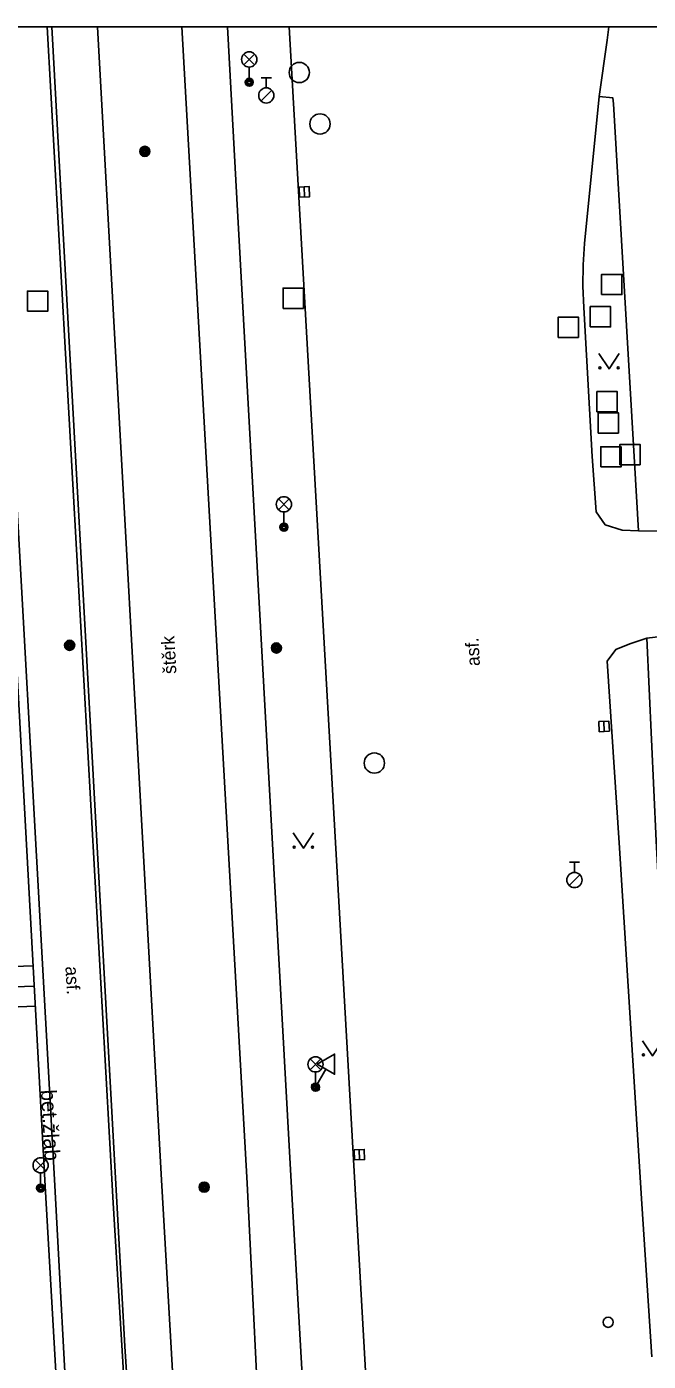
# Model space of a CAD drawing. Extents: x -599951 to -598963, y -1164095 to -1162939.
# Drawn here: x -599258.6 to -599227.9, y -1163005.2 to -1162939.4 of the extents above; entities that cross this region are included whole.
import ezdxf

# ---------------------------------------------------------------- set-up
doc = ezdxf.new("R2010")
doc.units = 0
for name, color, linetype in [('Level 10', 7, 'Continuous'), ('Level 11', 7, 'Continuous'), ('Level 13', 7, 'Continuous'), ('Level 15', 7, 'Continuous'), ('Level 25', 7, 'Continuous'), ('Level 26', 7, 'Continuous'), ('Level 27', 7, 'Continuous'), ('Level 28', 7, 'Continuous'), ('Level 33', 7, 'Continuous'), ('Level 34', 7, 'Continuous'), ('Level 36', 7, 'Continuous'), ('Level 40', 7, 'Continuous'), ('Level 42', 7, 'Continuous'), ('Level 9', 7, 'Continuous'), ('Vrstva 53', 7, 'Continuous')]:
    doc.layers.add(name, color=color, linetype=linetype)

msp = doc.modelspace()

# ---------------------------------------------------------------- linework, layer by layer
at = {"layer": 'Level 10'}
for points in [[(-599235.1, -1163108.54), (-599236.69, -1163094.1), (-599238.6, -1163065.25), (-599241.55, -1163010.92), (-599245.616, -1162939.4)], [(-599229.84, -1162939.4), (-599229.92, -1162940.07), (-599230.32, -1162942.84)], [(-599231.04, -1162950.09), (-599230.32, -1162942.84)], [(-599231.08, -1162953.26), (-599231.12, -1162952.2), (-599231.11, -1162951.15), (-599231.04, -1162950.09)], [(-599231.08, -1162953.26), (-599230.66, -1162960.61)], [(-599230.02, -1162963.97), (-599230.47, -1162963.34), (-599230.66, -1162960.61)], [(-599230.02, -1162963.97), (-599229.19, -1162964.24)], [(-599225.5, -1162964.29), (-599228.38, -1162964.28), (-599229.19, -1162964.24)], [(-599227.97, -1162969.57), (-599228.8, -1162969.84)], [(-599225.23, -1162969.24), (-599227.97, -1162969.57)], [(-599228.8, -1162969.84), (-599229.5, -1162970.13), (-599229.92, -1162970.71)], [(-599229.92, -1162970.71), (-599229.34, -1162979.66), (-599228.21, -1162997.48)], [(-599227.72, -1163005.03), (-599228.21, -1162997.48)]]:
    msp.add_lwpolyline(points, dxfattribs=at)
at = {"layer": 'Level 11'}
msp.add_line((-599257.324, -1162939.4), (-599256.84, -1162948.1), dxfattribs=at)
for points in [[(-599245.53, -1162996.1), (-599248.19, -1162947.88), (-599248.656, -1162939.4)], [(-599230.32, -1162942.84), (-599229.64, -1162942.91), (-599229.62, -1162943.2), (-599228.57, -1162960.89)], [(-599256.88, -1163010.08), (-599257.66, -1162996.31), (-599260.31, -1162948.14)], [(-599256.88, -1163010.08), (-599256.44, -1163010.06), (-599257.19, -1162996.28), (-599259.89, -1162948.12)], [(-599256.84, -1162948.1), (-599253.71, -1163004.52)], [(-599228.38, -1162964.28), (-599228.57, -1162960.89)], [(-599227.97, -1162969.57), (-599227.51, -1162979.56), (-599226.57, -1162997.39)], [(-599237.83, -1163111.49), (-599238.1, -1163108.93), (-599239.62, -1163094.44), (-599241.44, -1163069.14), (-599241.62, -1163064.75), (-599244.67, -1163011.13), (-599245.53, -1162996.1)], [(-599246.78, -1163110.11), (-599248.77, -1163090.46), (-599253.16, -1163012.98), (-599253.71, -1163004.52)]]:
    msp.add_lwpolyline(points, dxfattribs=at)
at = {"layer": 'Level 13'}
for p, q in [((-599255.061, -1162939.4), (-599251.92, -1162996.02)), ((-599247.68, -1162996.45), (-599250.903, -1162939.4))]:
    msp.add_line(p, q, dxfattribs=at)
for points in [[(-599251.92, -1162996.02), (-599251, -1163012.01), (-599248.49, -1163055.94), (-599247.39, -1163076.21), (-599246.85, -1163083.41), (-599245.99, -1163094.91), (-599244.38, -1163111.71)], [(-599240.22, -1163111.12), (-599241.9, -1163094.73), (-599243.24, -1163075.81), (-599243.89, -1163064.72), (-599246.94, -1163011.48), (-599247.68, -1162996.45)]]:
    msp.add_lwpolyline(points, dxfattribs=at)
at = {"layer": 'Level 15'}
for points in [[(-599261.63, -1162985.85), (-599258.24, -1162985.73)], [(-599261.59, -1162986.85), (-599258.18, -1162986.73)], [(-599261.56, -1162987.85), (-599258.13, -1162987.73)]]:
    msp.add_lwpolyline(points, dxfattribs=at)
at = {"layer": 'Level 25'}
for centre, radius in [((-599252.73, -1162945.55), 0.25), ((-599252.73, -1162945.55), 0.2), ((-599252.73, -1162945.55), 0.15), ((-599252.73, -1162945.55), 0.1), ((-599252.73, -1162945.55), 0.05), ((-599256.44, -1162969.92), 0.25), ((-599256.44, -1162969.92), 0.2), ((-599256.44, -1162969.92), 0.15), ((-599256.44, -1162969.92), 0.1), ((-599256.44, -1162969.92), 0.05), ((-599246.24, -1162970.05), 0.25), ((-599246.24, -1162970.05), 0.2), ((-599246.24, -1162970.05), 0.15), ((-599246.24, -1162970.05), 0.1), ((-599246.24, -1162970.05), 0.05), ((-599249.8, -1162996.65), 0.25), ((-599249.8, -1162996.65), 0.2), ((-599249.8, -1162996.65), 0.15), ((-599249.8, -1162996.65), 0.1), ((-599249.8, -1162996.65), 0.05)]:
    msp.add_circle(centre, radius, dxfattribs=at)
at = {"layer": 'Level 26'}
for points in [[(-599230.2, -1162952.62), (-599229.2, -1162952.62), (-599229.2, -1162951.62), (-599230.2, -1162951.62)], [(-599258.52, -1162953.44), (-599257.52, -1162953.44), (-599257.52, -1162952.44), (-599258.52, -1162952.44)], [(-599245.91, -1162953.3), (-599244.91, -1162953.3), (-599244.91, -1162952.3), (-599245.91, -1162952.3)], [(-599230.76, -1162954.21), (-599229.76, -1162954.21), (-599229.76, -1162953.21), (-599230.76, -1162953.21)], [(-599232.34, -1162954.73), (-599231.34, -1162954.73), (-599231.34, -1162953.73), (-599232.34, -1162953.73)], [(-599230.43, -1162958.4), (-599229.43, -1162958.4), (-599229.43, -1162957.4), (-599230.43, -1162957.4)], [(-599230.37, -1162959.45), (-599229.37, -1162959.45), (-599229.37, -1162958.45), (-599230.37, -1162958.45)], [(-599230.24, -1162961.12), (-599229.24, -1162961.12), (-599229.24, -1162960.12), (-599230.24, -1162960.12)], [(-599229.3, -1162961.01), (-599228.3, -1162961.01), (-599228.3, -1162960.01), (-599229.3, -1162960.01)]]:
    msp.add_lwpolyline(points, close=True, dxfattribs=at)
at = {"layer": 'Level 27'}
for p, q in [((-599244.869, -1162947.3), (-599244.851, -1162947.8)), ((-599230.093, -1162973.67), (-599230.067, -1162974.17)), ((-599242.159, -1162994.8), (-599242.141, -1162995.3))]:
    msp.add_line(p, q, dxfattribs=at)
for points in [[(-599245.119, -1162947.309), (-599245.101, -1162947.809), (-599244.601, -1162947.791), (-599244.619, -1162947.291)], [(-599230.343, -1162973.684), (-599230.316, -1162974.183), (-599229.817, -1162974.156), (-599229.844, -1162973.657)], [(-599242.409, -1162994.809), (-599242.391, -1162995.309), (-599241.891, -1162995.291), (-599241.909, -1162994.791)]]:
    msp.add_lwpolyline(points, close=True, dxfattribs=at)
for centre in [(-599245.11, -1162941.66), (-599244.09, -1162944.2), (-599241.41, -1162975.73)]:
    msp.add_circle(centre, 0.5, dxfattribs=at)
at = {"layer": 'Level 28'}
for p, q in [((-599246.99, -1162941.915), (-599246.49, -1162941.915)), ((-599246.74, -1162942.415), (-599246.74, -1162941.915)), ((-599246.998, -1162943.062), (-599246.468, -1162942.532)), ((-599231.79, -1162980.625), (-599231.29, -1162980.625)), ((-599231.54, -1162981.125), (-599231.54, -1162980.625)), ((-599231.798, -1162981.772), (-599231.268, -1162981.242))]:
    msp.add_line(p, q, dxfattribs=at)
for centre, radius in [((-599246.74, -1162942.79), 0.375), ((-599231.54, -1162981.5), 0.375), ((-599229.88, -1163003.32), 0.25)]:
    msp.add_circle(centre, radius, dxfattribs=at)
at = {"layer": 'Level 33'}
for p, q in [((-599247.845, -1162941.28), (-599247.315, -1162940.75)), ((-599247.845, -1162940.75), (-599247.315, -1162941.28)), ((-599247.58, -1162941.39), (-599247.58, -1162942.14)), ((-599246.135, -1162963.23), (-599245.605, -1162962.7)), ((-599246.135, -1162962.7), (-599245.605, -1162963.23)), ((-599245.87, -1162963.34), (-599245.87, -1162964.09)), ((-599244.575, -1162990.86), (-599244.045, -1162990.33)), ((-599244.575, -1162990.33), (-599244.045, -1162990.86)), ((-599244.31, -1162990.97), (-599244.31, -1162991.72)), ((-599258.135, -1162995.84), (-599257.605, -1162995.31)), ((-599258.135, -1162995.31), (-599257.605, -1162995.84)), ((-599257.87, -1162995.95), (-599257.87, -1162996.7))]:
    msp.add_line(p, q, dxfattribs=at)
for centre, radius in [((-599247.58, -1162941.015), 0.375), ((-599247.58, -1162942.14), 0.2), ((-599247.58, -1162942.14), 0.145), ((-599247.58, -1162942.14), 0.0876), ((-599245.87, -1162962.965), 0.375), ((-599245.87, -1162964.09), 0.2), ((-599245.87, -1162964.09), 0.145), ((-599245.87, -1162964.09), 0.0876), ((-599244.31, -1162990.595), 0.375), ((-599244.31, -1162991.72), 0.2), ((-599244.31, -1162991.72), 0.145), ((-599244.31, -1162991.72), 0.0876), ((-599257.87, -1162995.575), 0.375), ((-599257.87, -1162996.7), 0.2), ((-599257.87, -1162996.7), 0.145), ((-599257.87, -1162996.7), 0.0876)]:
    msp.add_circle(centre, radius, dxfattribs=at)
at = {"layer": 'Level 34'}
for p, q in [((-599243.803, -1162990.837), (-599244.31, -1162991.72)), ((-599244.527, -1162991.595), (-599244.093, -1162991.844))]:
    msp.add_line(p, q, dxfattribs=at)
msp.add_lwpolyline([(-599244.237, -1162990.588), (-599243.37, -1162991.086), (-599243.372, -1162990.086)], close=True, dxfattribs=at)
at = {"layer": 'Level 36'}
for points in [[(-599230.33, -1162955.53), (-599229.83, -1162956.28), (-599229.33, -1162955.53)], [(-599245.41, -1162979.18), (-599244.91, -1162979.93), (-599244.41, -1162979.18)], [(-599228.19, -1162989.43), (-599227.69, -1162990.18), (-599227.19, -1162989.43)]]:
    msp.add_lwpolyline(points, dxfattribs=at)
for centre in [(-599230.28, -1162956.23), (-599229.381, -1162956.23), (-599245.36, -1162979.88), (-599244.461, -1162979.88), (-599228.14, -1162990.13)]:
    msp.add_circle(centre, 0.05, dxfattribs=at)
at = {"layer": 'Level 9'}
msp.add_line((-599254.3, -1162997.42), (-599257.548, -1162939.4), dxfattribs=at)
msp.add_lwpolyline([(-599254.3, -1162997.42), (-599253.37, -1163012.58), (-599249.04, -1163089.47), (-599246.77, -1163112.49), (-599245.51, -1163121.3), (-599244.18, -1163129.29)], dxfattribs=at)
at = {"layer": 'Vrstva 53'}
msp.add_lwpolyline([(-599951.125, -1164094.695), (-598963.215, -1164094.695), (-598963.215, -1162939.4), (-599951.125, -1162939.4)], close=True, dxfattribs=at)

# ---------------------------------------------------------------- texts
at = {"layer": 'Level 40'}
for s, rotation, p in [('štěrk', 93.14131, (-599251.17, -1162971.32)), ('asf.', 93.14131, (-599236.2, -1162970.93)), ('asf.', 273.22352, (-599256.65, -1162985.77))]:
    msp.add_text(s, height=0.65, rotation=rotation, dxfattribs=at).set_placement(p)
at = {"layer": 'Level 42'}
msp.add_text('bet.žlab', height=0.75, rotation=273.20882, dxfattribs=at).set_placement((-599257.86, -1162991.86))

doc.saveas('drawing.dxf')
